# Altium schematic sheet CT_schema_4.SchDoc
size 493 x 398 mm
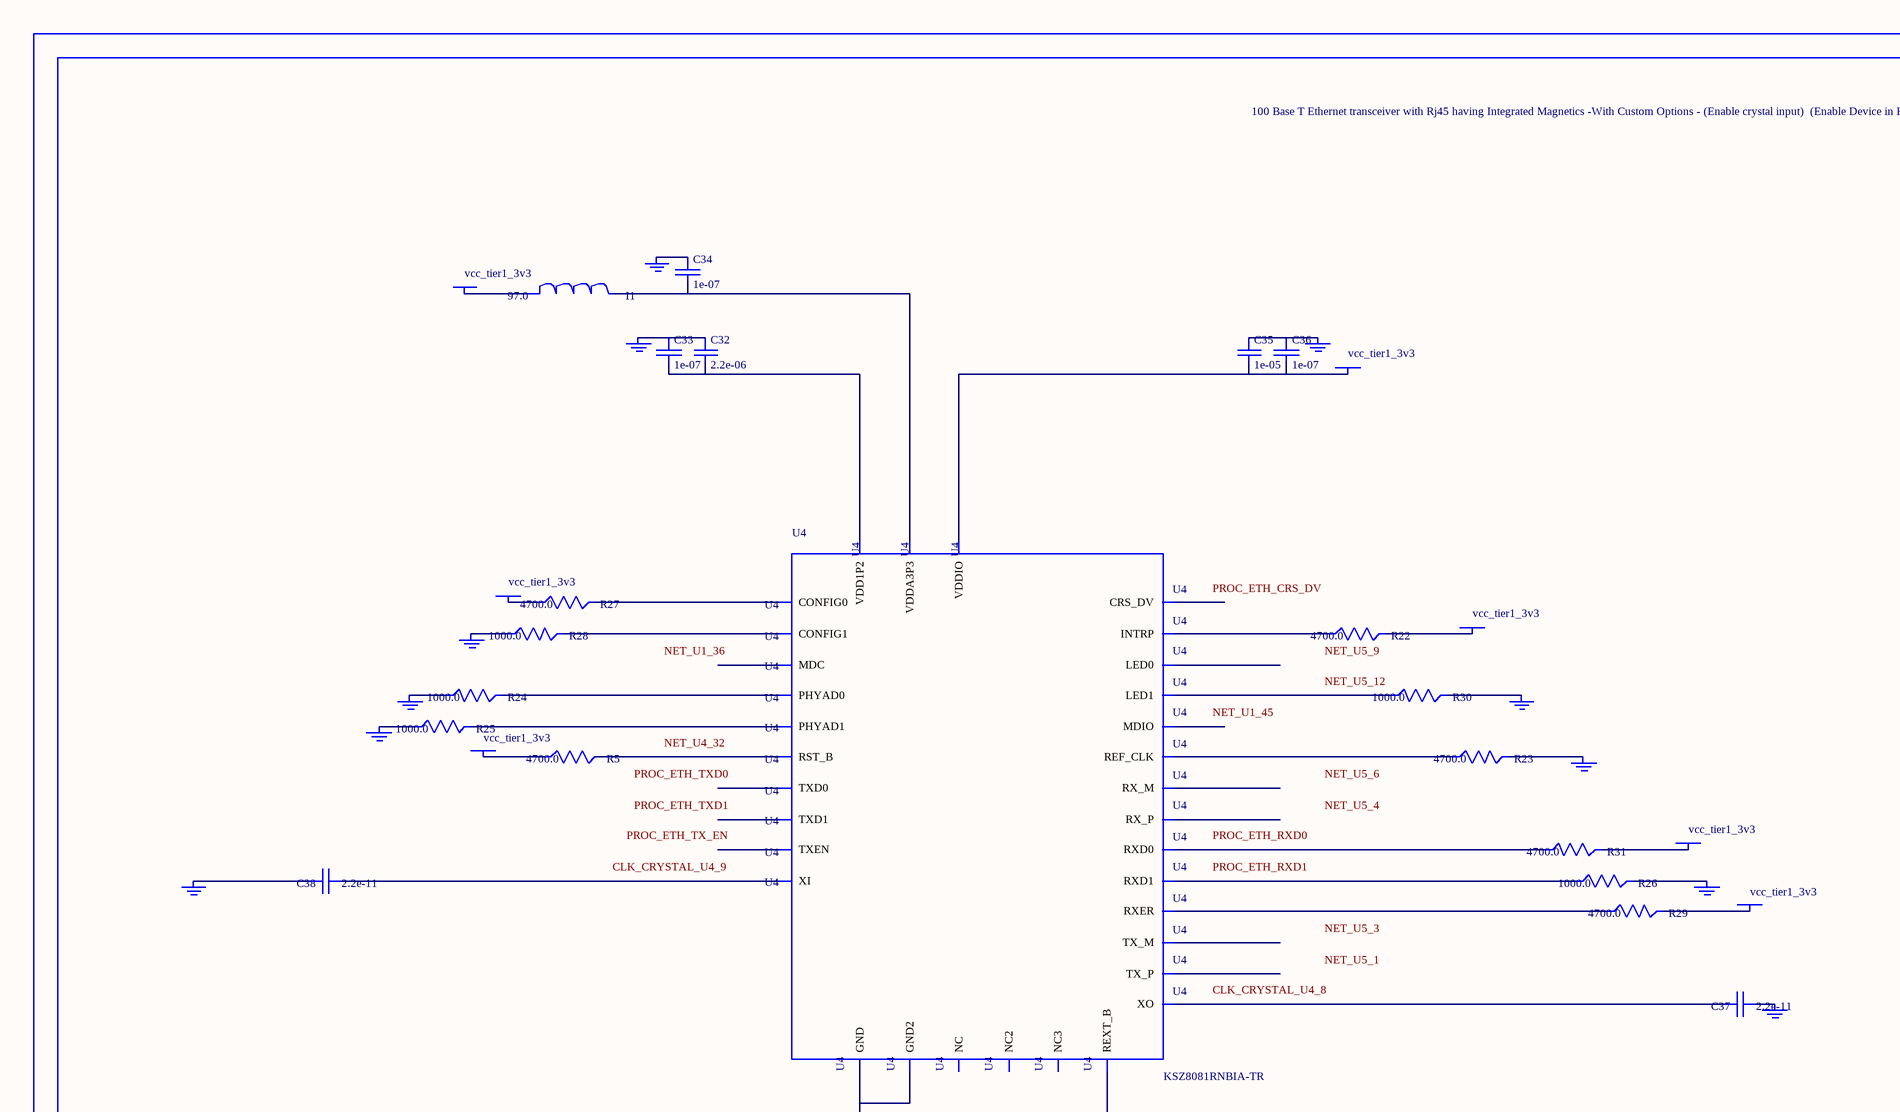
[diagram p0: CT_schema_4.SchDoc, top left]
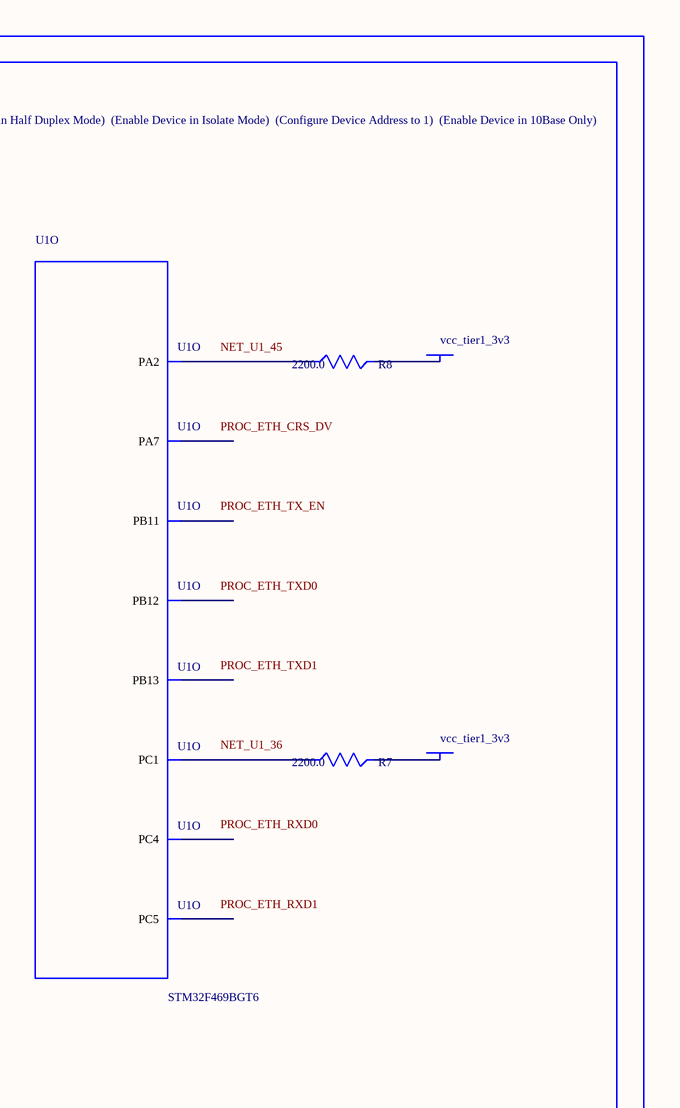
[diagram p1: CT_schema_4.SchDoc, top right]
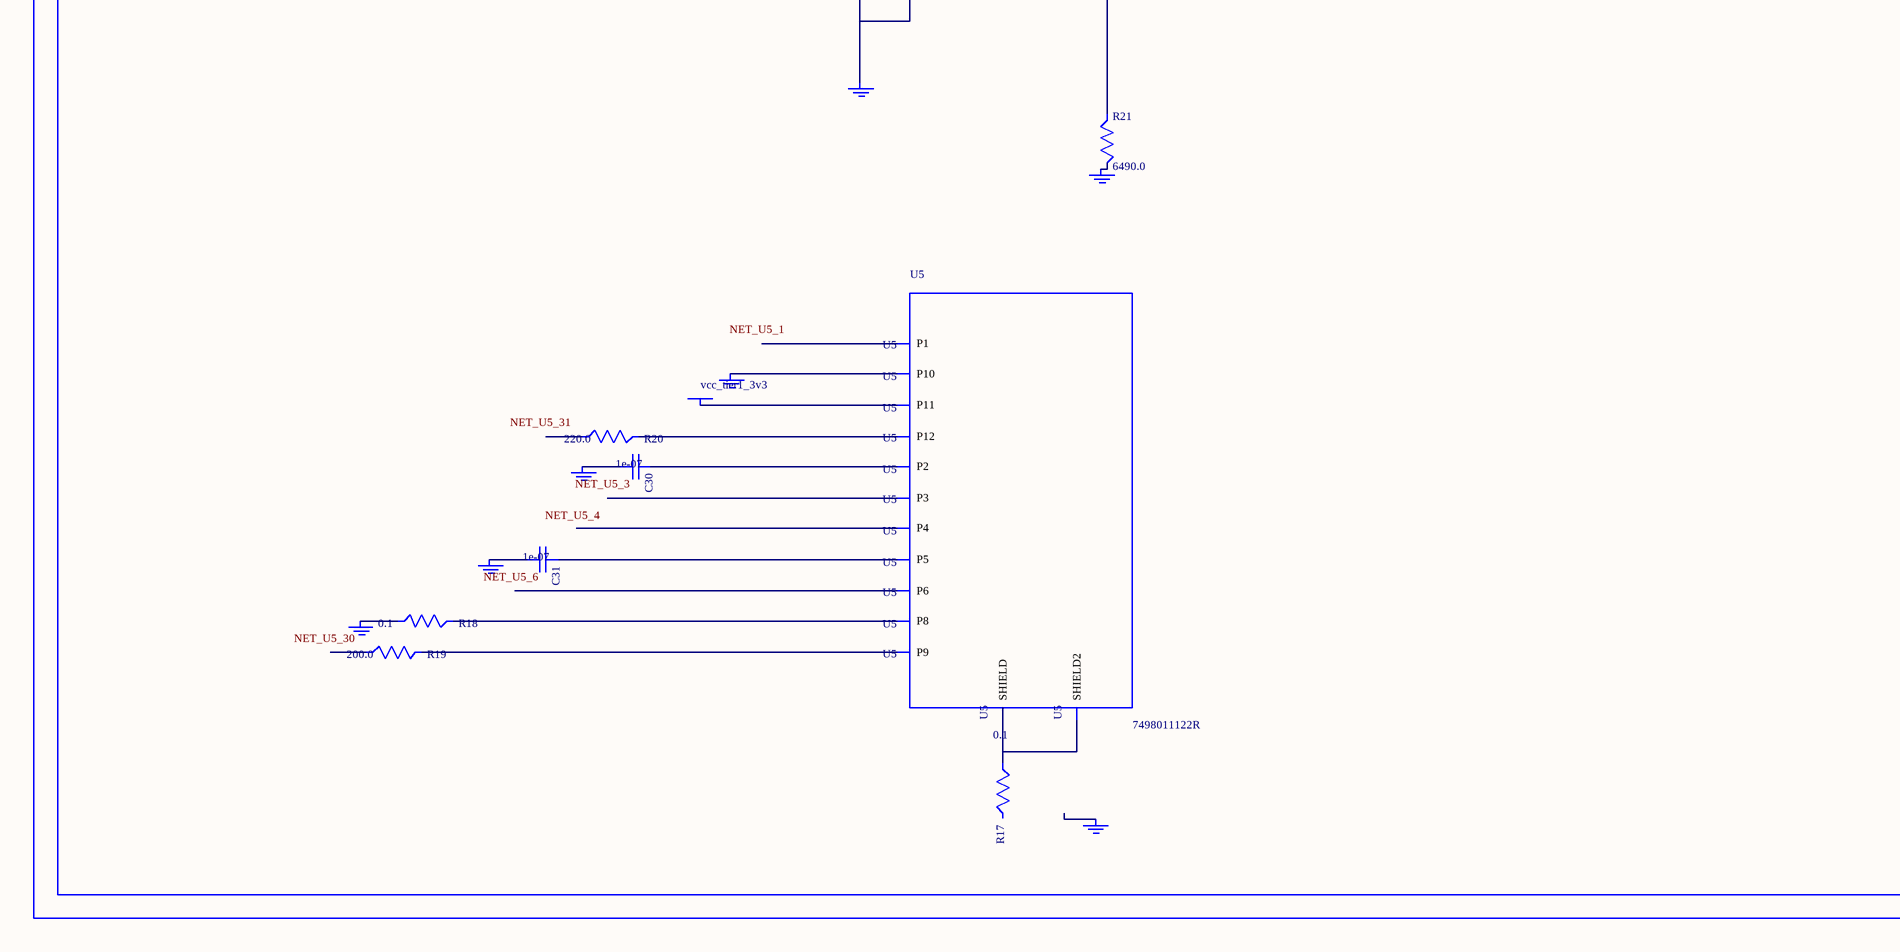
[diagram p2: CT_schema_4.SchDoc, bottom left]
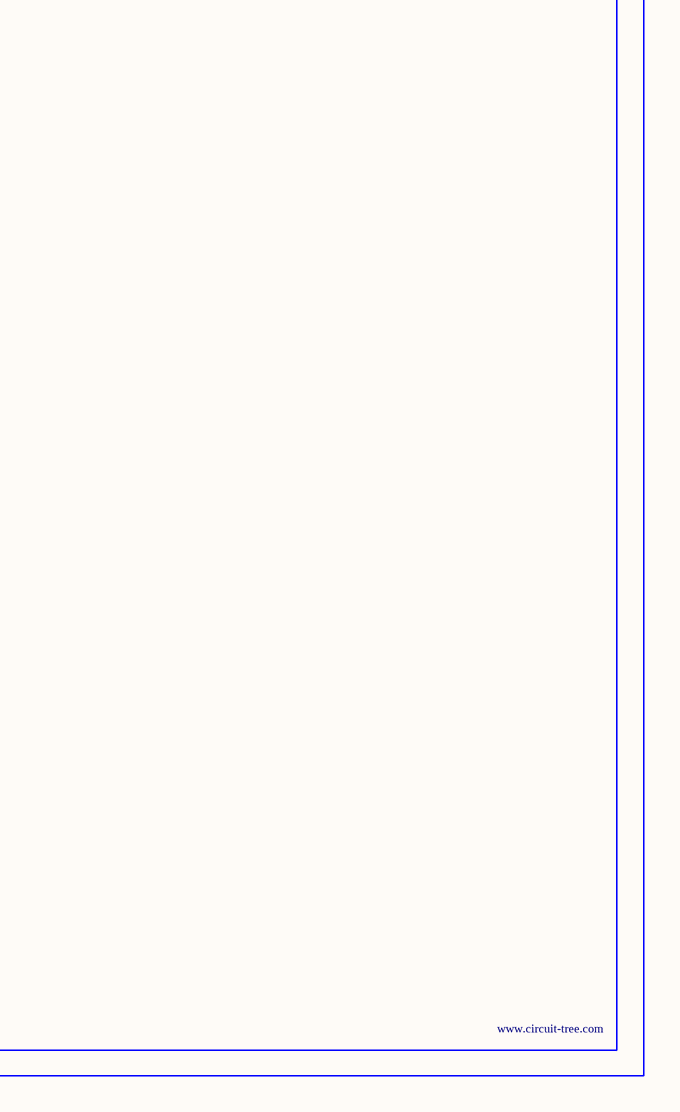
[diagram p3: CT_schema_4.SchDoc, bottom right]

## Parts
BORDER3  (no value)
C30  1e-07  [C0402]
C31  1e-07  [C0402]
C32  2.2e-06  [C0603]
C33  1e-07  [C0402]
C34  1e-07  [C0402]
C35  1e-05  [C0805]
C36  1e-07  [C0402]
C37  2.2e-11  [C0402]
C38  2.2e-11  [C0402]
GND_INSTANCE_3_0  (no value)
GND_INSTANCE_3_1  (no value)
GND_INSTANCE_3_2  (no value)
GND_INSTANCE_3_3  (no value)
GND_INSTANCE_3_4  (no value)
GND_INSTANCE_3_5  (no value)
GND_INSTANCE_3_6  (no value)
GND_INSTANCE_3_7  (no value)
GND_INSTANCE_3_8  (no value)
GND_INSTANCE_3_9  (no value)
GND_INSTANCE_3_10  (no value)
GND_INSTANCE_3_11  (no value)
GND_INSTANCE_3_12  (no value)
GND_INSTANCE_3_13  (no value)
GND_INSTANCE_3_14  (no value)
GND_INSTANCE_3_15  (no value)
GND_INSTANCE_3_16  (no value)
GND_INSTANCE_3_17  (no value)
I1  97.0  [R0603]
POWER_INSTANCE_3_0  vcc_tier1_3v3
POWER_INSTANCE_3_1  vcc_tier1_3v3
POWER_INSTANCE_3_2  vcc_tier1_3v3
POWER_INSTANCE_3_3  vcc_tier1_3v3
POWER_INSTANCE_3_4  vcc_tier1_3v3
POWER_INSTANCE_3_5  vcc_tier1_3v3
POWER_INSTANCE_3_6  vcc_tier1_3v3
POWER_INSTANCE_3_7  vcc_tier1_3v3
POWER_INSTANCE_3_8  vcc_tier1_3v3
POWER_INSTANCE_3_9  vcc_tier1_3v3
R5  4700.0  [R0603]
R7  2200.0  [R0603]
R8  2200.0  [R0603]
R17  0.1  [R0603]
R18  0.1  [R0603]
R19  200.0  [R0603]
R20  220.0  [R0603]
R21  6490.0  [R0603]
R22  4700.0  [R0603]
R23  4700.0  [R0603]
R24  1000.0  [R0603]
R25  1000.0  [R0603]
R26  1000.0  [R0603]
R27  4700.0  [R0603]
R28  1000.0  [R0603]
R29  4700.0  [R0603]
R30  1000.0  [R0603]
R31  4700.0  [R0603]
U1  STM32F469BGT6  [LQFP208]  (part O of 16)
U4  KSZ8081RNBIA-TR  [QFN-32]
U5  7498011122R  [7498011122R]

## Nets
NetC30_1: C30.1 U5.2(P2)
NetC30_2: C30.2 GND_INSTANCE_3_13.0(GND)
NetC31_1: C31.1 U5.5(P5)
NetC31_2: C31.2 GND_INSTANCE_3_14.0(GND)
NetC32_1: C32.1 C33.1 GND_INSTANCE_3_0.0(GND)
NetC32_2: C32.2 C33.2 U4.2(VDD1P2)
NetC34_1: C34.1 GND_INSTANCE_3_1.0(GND)
NetC34_2: C34.2 I1.2 U4.3(VDDA3P3)
NetC35_1: C35.1 C36.1 GND_INSTANCE_3_8.0(GND)
NetC35_2: C35.2 C36.2 POWER_INSTANCE_3_2.0(PWR) U4.17(VDDIO)
NetC37_1: C37.1 GND_INSTANCE_3_2.0(GND)
NetC37_2: C37.2 U4.8(XO)
NetC38_1: C38.1 U4.9(XI)
NetC38_2: C38.2 GND_INSTANCE_3_3.0(GND)
NetGND_INSTANCE_3_4_0: GND_INSTANCE_3_4.0(GND) R21.2
NetGND_INSTANCE_3_5_0: GND_INSTANCE_3_5.0(GND) R24.1
NetGND_INSTANCE_3_6_0: GND_INSTANCE_3_6.0(GND) R25.1
NetGND_INSTANCE_3_7_0: GND_INSTANCE_3_7.0(GND) R26.2
NetGND_INSTANCE_3_9_0: GND_INSTANCE_3_9.0(GND) R23.2
NetGND_INSTANCE_3_10_0: GND_INSTANCE_3_10.0(GND) R28.1
NetGND_INSTANCE_3_11_0: GND_INSTANCE_3_11.0(GND) R30.2
NetGND_INSTANCE_3_12_0: GND_INSTANCE_3_12.0(GND) U4.1(GND) U4.EXP(GND2)
NetGND_INSTANCE_3_15_0: GND_INSTANCE_3_15.0(GND) R18.1
NetGND_INSTANCE_3_16_0: GND_INSTANCE_3_16.0(GND) U5.10(P10)
NetI1_1: I1.1 POWER_INSTANCE_3_0.0(PWR)
NetPOWER_INSTANCE_3_1_0: POWER_INSTANCE_3_1.0(PWR) R31.2
NetPOWER_INSTANCE_3_3_0: POWER_INSTANCE_3_3.0(PWR) R29.2
NetPOWER_INSTANCE_3_4_0: POWER_INSTANCE_3_4.0(PWR) R22.2
NetPOWER_INSTANCE_3_5_0: POWER_INSTANCE_3_5.0(PWR) R27.1
NetPOWER_INSTANCE_3_6_0: POWER_INSTANCE_3_6.0(PWR) R5.1
NetPOWER_INSTANCE_3_7_0: POWER_INSTANCE_3_7.0(PWR) R7.2
NetPOWER_INSTANCE_3_8_0: POWER_INSTANCE_3_8.0(PWR) R8.2
NetPOWER_INSTANCE_3_9_0: POWER_INSTANCE_3_9.0(PWR) U5.11(P11)
NetR5_2: R5.2 U4.32(RST_B)
NetR7_1: R7.1 U1.36(PC1)
NetR8_1: R8.1 U1.45(PA2)
NetR17_1: R17.1 U5.13(SHIELD) U5.14(SHIELD2)
NetR18_2: R18.2 U5.8(P8)
NetR19_2: R19.2 U5.9(P9)
NetR20_2: R20.2 U5.12(P12)
NetR21_1: R21.1 U4.10(REXT_B)
NetR22_1: R22.1 U4.21(INTRP)
NetR23_1: R23.1 U4.19(REF_CLK)
NetR24_2: R24.2 U4.13(PHYAD0)
NetR25_2: R25.2 U4.14(PHYAD1)
NetR26_1: R26.1 U4.15(RXD1)
NetR27_2: R27.2 U4.28(CONFIG0)
NetR28_2: R28.2 U4.29(CONFIG1)
NetR29_1: R29.1 U4.20(RXER)
NetR30_1: R30.1 U4.31(LED1)
NetR31_1: R31.1 U4.16(RXD0)

Not connected (* = marked no-connect by the designer): GND_INSTANCE_3_17 0(GND); R17 2; R19 1; R20 1; U1 56(PA7) 57(PC4) 58(PC5) 91(PB11) 104(PB12) 105(PB13); U4 4(RX_M) 5(RX_P) 6(TX_M) 7(TX_P) 11(MDIO) 12(MDC) 18(CRS_DV) 22(NC) 23(TXEN) 24(TXD0) 25(TXD1) 26(NC2) 27(NC3) 30(LED0); U5 1(P1) 3(P3) 4(P4) 6(P6)

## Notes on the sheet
- Labels drawn without touching a wire or pin: CLK_CRYSTAL_U4_8, CLK_CRYSTAL_U4_9, NET_U1_36, NET_U1_45, NET_U4_32, NET_U5_1, NET_U5_3, NET_U5_4, NET_U5_6, NET_U5_9, NET_U5_12, NET_U5_30, NET_U5_31, PROC_ETH_CRS_DV, PROC_ETH_RXD0, PROC_ETH_RXD1, PROC_ETH_TX_EN, PROC_ETH_TXD0, PROC_ETH_TXD1

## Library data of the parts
BORDER3 = BORDER_PAGE3
C30 C31 C33 C34 C36 = C0402C104K3RACTU
C32 = C0603C225K8RACTU
C35 = C0805C106K8RACTU
C37 C38 = C0402C220K3RAC
GND_INSTANCE_3_0-GND_INSTANCE_3_17 = GND
I1 = I1
POWER_INSTANCE_3_0-POWER_INSTANCE_3_9 = PWR
R5 R22 R23 R27 R29 R31 = RC0603JR-074K7L
R7 R8 = RC0603JR-072K2L
R17 R18 = ERJ-3RSFR10V
R19 = RC0603JR-07200RL
R20 = RC0603JR-07220RL
R21 = ERJ-3EKF6491V
R24-R26 R28 R30 = RC0603JR-071KL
